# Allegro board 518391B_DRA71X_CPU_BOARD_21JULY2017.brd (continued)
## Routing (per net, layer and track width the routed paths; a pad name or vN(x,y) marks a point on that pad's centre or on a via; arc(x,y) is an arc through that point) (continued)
N30649045: length 1.8
  TOP w0.127: U44.8 158.47,31.43 v2(158.66,31.62)
  BOTTOM w0.127: 158.12,30.86 158.12,31.07 v2(158.66,31.62)
N30649515: length 4.2
  TOP w0.127: U44.6 156.68,30.06 v2(156.64,30.03) 157.08,29.59 157.35,29.59 C227.1
  BOTTOM w0.127: R379.1 156.97,30.36 v2(156.64,30.03)
N30674781: length 9.8
  TOP w0.127: R105.2 J10.1 ; U33.5 v2(153.15,56.64)
  BOTTOM w0.127: v2(153.15,56.64) 152.95,56.85 152.95,57.62 152.4,58.17 152.4,58.8 151.76,59.44 149.99,59.44 149.61,59.05 J10.1
N30703324: length 4.5
  TOP w0.254: R1.2 128.02,152.53 127.94,152.45 C7.1 125.71,151.04 U11.12
N30703458: length 2
  TOP w0.127: U11.19 122.31,148.47 122.05,148.21 R4.1
N30703463: length 2.3
  TOP w0.127: U11.20 122.57,147.97 121.67,147.07 R5.1
N30746595: length 1.8
  TOP w0.127: RJ1.2 128.27,149.61 128.13,149.46 U11.10
N30797231: length 1.6
  TOP w0.254: U20.6 105.33,116.72 105.45,116.84 C62.1
N30798114: length 1.7
  TOP w0.254: C245.1 92.46,25.38 92.51,25.43 92.33,25.61 U48.6
N30809211: length 5.1
  TOP w0.203: C220.2 R140.1 R141.2 88.04,32.61 88.04,34.04 88.3,34.29 U42.3
N30811250: length 6.8
  TOP w0.305: R182.2 161.8,15.19 161.49,15.49 U50.5 160.4,13.97 R177.1 RJ15.2
N30811520: length 2.2
  TOP w0.305: U50.3 C256.1
N30812987: length 2.4
  TOP w0.305: C255.1 153.16,18.03 U50.2
N30812990: length 1.5
  TOP w0.305: R163.1 151.13,19.68 C255.2
N30812993: length 1.8
  TOP w0.305: R163.2 154.18,19.94
N30813342: length 6
  TOP w0.305: R176.1 C257.1 R175.1 152.4,15.06 152.83,15.49 U50.4
N30813649: length 2.4
  TOP w0.305: R172.1 R175.2 C257.2
N30818369: length 4.1
  TOP w0.305: U43.14 146.98,30.18 147.57,29.59 R148.2 R149.2
N30818430: length 2.6
  TOP w0.305: R147.2 146.3,30.1 146.33,30.13 U43.13
N30818444: length 2.9
  TOP w0.305: R146.2 145.03,29.59 145.68,30.24 U43.12
N30819162: length 4.1
  TOP w0.305: R158.2 R159.2 139.95,21.46 140.54,20.87 U51.14
N30819197: length 1.4
  TOP w0.127: R159.1 TP58.1
N30819223: length 2.6
  TOP w0.305: R160.2 141.22,20.95 141.19,20.92 U51.13
N30819237: length 2.9
  TOP w0.305: U51.12 141.84,20.81 142.49,21.46 R161.2
N30821669: length 2.8
  TOP w0.203: U42.5 91.17,33.79 91.57,33.4 91.57,32.77 92.33,32
N31193882: length 2.3
  TOP w0.305: R14.1 44.74,136.23 Q6.4
N31194203: length 5.8
  TOP w0.305: Q4.4 v2(54.19,133.9) ; R20.1 v2(56.9,131.7)
  BOTTOM w0.305: v2(56.9,131.7) 55.5,131.7 54.19,133.01 v2(54.19,133.9)
N31194290: length 3.2
  TOP w0.305: Q5.4 57.87,132.88 58.17,132.59 R21.2
N31194295: length 6.3
  TOP w0.305: v2(64.26,136.23) 64.3,136.27 R15.2 ; Q7.4 v2(59.6,136.23)
  BOTTOM w0.305: v2(59.6,136.23) v2(64.26,136.23)
N31194655: length 2.3
  TOP w0.203: D9.1 45.03,112.83 R42.1
N31194670: length 7.3
  TOP w0.203: U19.2 49.38,111.79 ; 49.38,111.79 49.91,111.27 C67.1 ; 49.38,111.79 47.97,111.79 47.5,112.27 R42.2
N31194787: length 7.3
  TOP w0.305: D8.1 47.17,123.88 46.74,123.44 C50.1 48.89,122.55 50.03,121.42 U19.26
N31194818: length 7.3
  TOP w0.305: U19.20 53.93,121.5 54.23,121.79 C47.2 54.23,123.57 53.92,123.88 D6.1 53.92,126.75 D4.1
N31196095: length 3.7
  TOP w0.203: R37.1 60.07,120.14 59.93,120 59.33,120 C55.2 59.29,120.03 58.31,120.03 58.17,119.89 U19.15
N31196104: length 5.5
  TOP w0.203: R38.1 60.69,118.86 59.96,118.86 59.82,119 C55.1 58.29,119 57.91,118.62 56.77,118.62 56.54,118.85 U19.16
N31196146: length 8.7
  TOP w0.203: U19.7 52.63,112.58 v2(52.45,112.39) ; C74.1 v2(53.09,106.43)
  BOTTOM w0.203: v2(53.09,106.43) 52.45,107.06 v2(52.45,112.39)
N31196169: length 10.1
  TOP w0.203: R54.1 51.18,106.3 50.67,105.79 50.67,105.79 v2(50.67,105.78) ; U19.5 51.33,112.55 v2(51.12,112.33)
  BOTTOM w0.203: v2(50.67,105.78) 50.67,105.79 50.67,107.31 51.94,108.58 51.94,111.51 v2(51.12,112.33)
N31196187: length 10.3
  TOP w0.203: C76.2 v2(50.16,106.3) ; U19.6 51.98,112.94 51.82,112.78 51.82,112.01 51.31,111.51 v2(51.31,110.74) 51.31,110.24 51.43,110.11 R50.1
  BOTTOM w0.203: v2(50.16,106.3) 50.16,107.7 51.31,108.84 v2(51.31,110.74)
N31196205: length 10.4
  TOP w0.203: U19.4 50.68,112.66 50.55,112.52 v2(50.55,111.76) ; R53.1 v2(47.62,107.31) 47.24,107.7 R48.1
  BOTTOM w0.203: v2(50.55,111.76) 50.55,110.24 v2(47.62,107.31)
N31196259: length 4.4
  TOP w0.203: U19.9 53.93,111.17 R44.2 53.99,111.11 53.99,110.25 53.85,110.11 C69.1
N31196266: length 1.5
  TOP w0.203: R44.1 52.45,110.4 52.59,110.26 52.59,109.74 C68.1
N31197066: length 9.1
  TOP w0.203: U19.8 v2(53.28,112.39) ; C75.1 v2(54.8,106.43)
  BOTTOM w0.203: v2(54.8,106.43) 53.28,107.94 v2(53.28,112.39)
N31197134: length 6.8
  TOP w0.203: C70.2 48.64,109.98 v2(48.64,111) R45.2 ; U19.3 v2(50.03,112.39)
  BOTTOM w0.203: v2(50.03,112.39) v2(48.64,111)
N31197473: length 3.5
  TOP w0.203: TP14.1 R46.1 61.71,111.52 60.85,111.52 60.71,111.38 R43.2
N31206842: length 11.8
  TOP w0.305: U16.6 20.41,132.14 19.94,132.61 19.94,133.1 18.03,135 16.26,135 ; 16.26,135 15.75,134.49 15.75,133.09 16.05,132.79 U16.2 ; 16.26,135 Q3.4
N31206856: length 5.5
  TOP w0.305: U16.1 18.4,133.44 18.67,133.17 C30.1
N31206860: length 6
  TOP w0.305: U16.7 22.9,132.79 23.37,132.32 23.37,130.3 22.35,129.29 C30.2
N31206880: length 21.3
  TOP w0.635: L4.1 26.66,136.52 ; L4.1 23.38,136.52 ; L4.1 25.02,138.16 ; L4.1 25.02,134.89
  BOTTOM w0.127: v2(21.08,141.1) 19.05,143.13 11.68,143.13 11.18,143.64 11.18,146.05 10.67,146.56 10.03,146.56
N31207095: length 2.1
  TOP w0.127: v2(8.25,146.56) 8.41,146.71 DS1.2
  BOTTOM w0.127: v2(8.25,146.56) R202.1
N31208453: length 2.7
  TOP w0.203: U18.13 v2(81.28,126.87)
  BOTTOM w0.203: v2(81.28,126.87) 81.28,128.02 R213.2
N31208462: length 2
  TOP w0.203: v2(80.52,127.76) 80.12,127.37 U18.14
  BOTTOM w0.203: v2(80.52,127.76) 80.77,128.02 R214.1
N31208471: length 2.9
  TOP w0.203: v2(82.42,123.57) 81.77,124.22 U18.8
  BOTTOM w0.203: R219.2 82.93,123.06 v2(82.42,123.57)
N31208480: length 1.8
  TOP w0.203: v2(81.79,123.06) 81.79,123.52 81.58,123.72 U18.7
  BOTTOM w0.203: R220.1 v2(81.79,123.06)
N31208503: length 13.8
  LY3 w0.305: v2(93.81,122.47) 92.63,121.28 v2(83.69,121.28)
  BOTTOM w0.305: v2(83.69,121.28) R219.1 R220.2 ; Q10.4 v2(93.81,122.47)
N31208524: length 7.6
  BOTTOM w0.305: R214.2 R213.1 82.5,129.67 82.8,129.36 82.8,128.52 85.18,126.15 Q9.4
N31208551: length 15.6
  TOP w0.203: U18.12 81.89,126.21 82.17,126.49 v2(82.17,127) 82.8,127.63 C39.1 ; R18.1 v2(78.61,132.46)
  LY4 w0.203: v2(82.17,127) 80.77,128.4 80.77,130.3 v2(78.61,132.46)
  BOTTOM w0.203: v2(82.17,127) 85.72,123.44
  vias: v2(87.12,124.21) v2(87.12,123.32) v2(87.88,124.21) v2(87.88,123.32) v2(88.65,124.21) v2(88.65,123.32) v2(90.3,124.21) v2(90.3,123.44) v2(90.3,122.68) v2(91.19,124.21) v2(91.19,123.44) v2(91.19,122.68)
N31208672: length 3.8
  TOP w0.203: D5.1 C39.2 82.79,125.71 U18.11
N31208960: length 1.4
  BOTTOM w0.508: 88.65,119.89 R225.1
N31209649: length 6.2
  TOP w0.203: R18.2 R428.1 C36.2 76.71,128.52 78.13,127.1 U18.18
N31209654: length 4.8
  TOP w0.203: U18.17 78.63,127.37 77.72,128.27 C36.1 R22.1 R428.2
N31222073: length 5.2
  TOP w0.203: U18.23 77.01,124.22 76.71,123.92 v2(76.71,123.32) 75.95,122.55 C48.2
  BOTTOM w0.203: R401.1 76.07,122.68 v2(76.71,123.32)
  BOTTOM w0.254: R218.1 v2(76.71,123.32)
N31222132: length 1.4
  TOP w0.203: R29.1 75.44,124.97 C41.2
N31222198: length 3.5
  TOP w0.203: U18.20 76.85,125.71 76.45,126.11 R29.2 74.3,126.11 C40.1
N31222241: length 3.5
  TOP w0.203: C51.2 75.95,121.41 77.47,122.94 U18.24
N31222246: length 2.5
  TOP w0.203: U18.22 76.97,124.72 75.95,123.7 C43.2
N31222265: length 3.6
  TOP w0.203: R36.2 R35.1 81.47,121.48 81.47,121.86 80.62,122.71 U18.6
N31222285: length 3.4
  TOP w0.203: U18.5 80.12,122.57 80.47,122.23 80.47,121.61 C54.2 R34.1
N31222303: length 2.1
  TOP w0.203: v2(79.76,122.05) 79.62,122.18 U18.4
  BOTTOM w0.203: R222.2 v2(79.76,122.05)
N31222717: length 1.1
  TOP w0.203: R24.2 R23.1
N31223527: length 2.4
  BOTTOM w0.305: v2(86.49,137.54) 86.87,137.92 R211.1 R209.1
N31223584: length 3.9
  TOP w0.305: U15.5 92.02,138.23 92.08,138.18 v2(92.08,137.92) C27.1
  BOTTOM w0.305: R210.1 v2(92.08,137.92)
N31223889: length 1.3
  TOP w0.305: R16.1 C26.2
N31224124: length 3.4
  TOP w0.127: v2(95.25,145.67) 94.81,145.23 U15.9
  BOTTOM w0.127: R204.2 R207.1 v2(95.25,145.67)
N31225374: length 4.3
  TOP w0.127: R10.2 126.62,144.02 126.62,146.15 126.21,146.56 U11.6
N31225630: length 3.6
  TOP w0.305: U15.11 v2(92.67,146.52)
  BOTTOM w0.305: R208.2 92.67,145.33 v2(92.67,146.52)
N31225660: length 4.5
  TOP w0.305: RJ2.2 R17.1 93.6,137.41 93.22,137.41 92.67,137.96 U15.6
N31226612: length 6.8
  TOP w0.127: U15.7 93.32,138.2 v2(93.54,137.99)
  TOP w0.305: C28.2 91.82,137.22 v2(91.37,137.67) U15.4
  BOTTOM w0.127: v2(93.54,137.99) 92.84,137.29 91.75,137.29 v2(91.37,137.67)
N31272257: length 2.5
  TOP w0.127: 118.49,95.99 117.87,95.99 R59.2 ; 118.49,95.99 U24.2 ; 118.49,95.99 118.49,95.76 118.76,95.49 U24.3
N31313642: length 3.4
  TOP w0.127: U11.8 127.38,148.47 127.63,148.21 127.63,147.83 128.27,147.19 R8.2
N31313645: length 4.6
  TOP w0.127: U11.9 127.77,148.97 128.02,148.72 128.02,148.21 129.29,146.94 R9.2
N31432046: length 1.3
  TOP w0.127: R148.1 TP54.1
N31435823: length 2.3
  TOP w0.127: U37.44 v2(132.24,50.45)
  BOTTOM w0.127: R317.1 132.24,51.28 v2(132.24,50.45)
N31460069: length 3.1
  TOP w0.127: Q8.6 88.25,41.16 v2(88.52,40.89) 88.14,40.51 Q8.5
  BOTTOM w0.127: R370.1 88.39,41.02 v2(88.52,40.89)
N31485198: length 2.1
  TOP w0.127: R67.1 153.18,86.09 U25.21
N31485201: length 2.1
  TOP w0.127: U25.20 153.23,87.19 R65.1
N31485220: length 8.4
  TOP w0.127: U25.3 v2(168.38,84.99) ; v2(167.89,78.99) R69.2
  BOTTOM w0.127: v2(168.38,84.99) 168.38,79.48 v2(167.89,78.99)
N31486138: length 2.7
  TOP w0.127: U75.2 116.08,94.23 RJ5.2
N31555915: length 2.3
  BOTTOM w0.305: R211.2 R209.2 C265.1
N31573832: length 8.7
  TOP w0.508: C208.1 v2(69.6,36.07) ; RJ12.2 v2(65.02,36.83) L36.1 65.02,35.84
  BOTTOM w0.508: C516.1 v2(69.6,36.07) 68.83,36.83 v2(65.02,36.83)
N31594961: length 7.1
  TOP w0.305: R142.2 C206.2 ; C206.2 66.67,34.16 R137.2 ; C206.2 70.61,34.16 71.05,34.6 U41.3
N31595589: length 3.5
  TOP w0.127: U41.6 75.51,34.6 75.69,34.42 75.69,32.51 C218.1
N31598114: length 8.7
  TOP w0.508: L52.1 v2(65.02,29.34) RJ13.2 ; v2(69.6,28.59) C241.1
  BOTTOM w0.508: 69.6,27.69 v2(69.6,28.59) 68.85,29.34 v2(65.02,29.34)
N31598152: length 3.5
  TOP w0.127: U49.6 75.51,27.11 75.69,26.92 75.69,25.02 C246.1
N31598156: length 7.1
  TOP w0.305: R150.2 66.67,26.67 C236.2 ; C236.2 70.61,26.67 71.05,27.11 U49.3 ; C236.2 R157.2
N31635389: length 6.7
  TOP w0.127: P8.2 v2(10.08,12.52)
  BOTTOM w0.127: v2(10.08,12.52) 10.08,13.54 C534.2 11.29,13.59 U65.1 12.56,13.6 R399.1 12.7,13.46 C535.2
N31635587: length 8
  TOP w0.127: P8.3 v2(6.22,19.68)
  BOTTOM w0.127: v2(6.22,19.68) C532.1 7.48,18.41 U64.1 8.75,18.4 R396.2 R395.2 11.05,18.41 C531.2
N31636337: length 6.7
  TOP w0.127: P7.2 v2(10.08,23.95)
  BOTTOM w0.127: v2(10.08,23.95) 10.08,24.97 C529.2 11.29,25.02 U63.1 12.56,25.03 R392.1 12.7,24.89 C530.2
N31636510: length 8
  TOP w0.127: P7.3 v2(6.22,31.11)
  BOTTOM w0.127: C520.2 11.05,29.84 R385.2 R386.2 8.75,29.83 U62.1 7.48,29.84 C523.1 v2(6.22,31.11)
N31636885: length 6.7
  TOP w0.127: P6.2 v2(10.08,35.38)
  BOTTOM w0.127: v2(10.08,35.38) 10.08,36.4 C512.2 11.29,36.45 U61.1 12.56,36.46 R366.1 12.7,36.32 C513.2
N31637058: length 8
  TOP w0.127: P6.3 v2(6.22,42.54)
  BOTTOM w0.127: v2(6.22,42.54) C504.1 7.48,41.27 U60.1 8.75,41.26 R353.2 R352.2 11.05,41.27 C502.2
N31637886: length 6.7
  TOP w0.127: P4.2 v2(10.08,46.81)
  BOTTOM w0.127: C490.2 12.7,47.75 R326.1 12.56,47.89 U59.1 11.29,47.88 C489.2 10.08,47.83 v2(10.08,46.81)
N31638056: length 8
  TOP w0.127: P4.3 v2(6.22,53.97)
  BOTTOM w0.127: C473.2 11.05,52.7 R314.2 R315.2 8.75,52.69 U58.1 7.48,52.7 C476.1 v2(6.22,53.97)
N31638108: length 6.7
  TOP w0.127: P3.2 v2(10.08,58.24)
  BOTTOM w0.127: C449.2 12.7,59.18 R304.1 12.56,59.32 U57.1 11.29,59.31 C448.2 10.08,59.26 v2(10.08,58.24)
N31638278: length 8
  TOP w0.127: P3.3 v2(6.22,65.41)
  BOTTOM w0.127: v2(6.22,65.41) C439.1 7.48,64.13 U53.1 8.75,64.12 R294.2 R293.2 11.05,64.13 C438.2
N31691908: length 4
  TOP w0.127: R57.1 TP20.1 124.46,92.96 123.93,93.49 U24.10
N31691918: length 7.1
  TOP w0.127: U24.12 124.47,94.49 124.71,94.74 TP22.1 126.87,94.74 R58.1 R60.1
N31691928: length 6.9
  TOP w0.127: U24.13 124.08,94.99 124.71,95.63 TP23.1 126.87,95.88 R62.1 R61.1
N31691937: length 6.1
  TOP w0.127: U75.4 v2(114.71,90.45)
  LY3 w0.133: TP24.1 118.24,90.3 117.94,90 115.15,90 v2(114.71,90.45)
  BOTTOM w0.127: R63.1 115.42,90.45 v2(114.71,90.45)
N31767762: length 2.5
  TOP w0.127: v2(133.22,53.21) 132.74,52.73 U37.43
  BOTTOM w0.127: v2(133.22,53.21) R316.2
N31975868: length 16.5
  TOP w0.127: U27.F20 v1(88.09,79.83)
  LY4 w0.133: v1(88.09,79.83) 88.7,79.23 88.7,77.9 85.7,74.9 84.71,74.9 84.14,74.34 83.51,74.34 82.59,73.43 82.37,73.43 81.88,72.94 77.51,72.94 TP32.1
N32186036: length 1.6
  TOP w0.254: U39.6 69.21,43.98 69.09,44.11 C174.1
N32241906: length 2
  TOP w0.127: R168.1 67.22,13.25 v2(67.22,13.93)
  BOTTOM w0.127: v2(67.22,13.93) 67.49,13.67 J19.119
N32242118: length 5.6
  TOP w0.127: RJ30.3 v2(80.26,22.61)
  BOTTOM w0.127: v2(80.26,22.61) 80.26,21.08 79.49,20.31 J19.22
N32242181: length 3.3
  BOTTOM w0.127: TP61.1 85.6,19.68 85.49,19.57 J19.32
N32242306: length 1.9
  TOP w0.127: v2(92.74,13.94) 92.74,13.23 R165.1
  BOTTOM w0.127: v2(92.74,13.94) 92.68,13.89 J19.77
N32242319: length 1.5
  TOP w0.127: D20.1 R169.1
N32242321: length 2.6
  TOP w0.127: v2(92.96,19.81) D20.2
  BOTTOM w0.127: J19.45 93.28,19.49 v2(92.96,19.81)
N32242323: length 3.7
  BOTTOM w0.127: J19.76 93.28,14.41 92.33,15.37 TP59.1
N32242357: length 1.9
  TOP w0.127: R164.1 95.09,13.24 v2(95.09,13.94)
  BOTTOM w0.127: v2(95.09,13.94) 95.08,13.93 J19.73
N32242411: length 2.2
  TOP w0.127: v2(100.2,19.43) 100.33,19.3 R184.1
  BOTTOM w0.127: J19.57 100.48,19.16 v2(100.2,19.43)
N32256405: length 2.6
  TOP w0.127: RJ14.2 94.87,17.65 94.53,17.31 v2(94.53,16.93)
  BOTTOM w0.127: v2(94.53,16.93) 94.48,16.98 J19.47
N32396399: length 5.6
  TOP w0.127: U33.47 156.56,54.32 158.37,56.13 159.51,56.13 TP38.1
N32396462: length 5.2
  BOTTOM w0.127: TP43.1 158.37,43.18 158.37,45.59 R336.2 157.99,46.99
N32396466: length 4.9
  BOTTOM w0.127: TP44.1 158.75,42.42 158.75,45.72 R336.1 159,46.99
N32396489: length 4.2
  TOP w0.127: v2(157.1,50.16) 156.94,50.32 U33.39
  BOTTOM w0.127: C491.1 158.62,48.39 158.62,48.64 v2(157.1,50.16)
N32396498: length 3.5
  TOP w0.127: U33.38 156.68,49.82 v2(156.97,49.53)
  BOTTOM w0.127: v2(156.97,49.53) 157.23,49.53 158.24,48.51 158.24,48.26 C492.1
N32412234: length 6.8
  TOP w0.127: R110.2 157.99,54.86 157.61,54.48 ; 157.61,54.48 157.61,52.45 157.35,52.2 156.84,52.2 156.72,52.32 U33.43 ; 157.61,54.48 157.4,54.48 156.73,53.82 U33.46
N32413360: length 2.4
  TOP w0.127: v2(80.77,19.56) 80.77,18.54
  BOTTOM w0.127: J19.24 80.69,19.47 v2(80.77,19.56)
N32413363: length 2.4
  TOP w0.127: v2(81.53,19.43) 81.91,19.05 81.91,18.54
  BOTTOM w0.127: v2(81.53,19.43) 81.29,19.18 J19.25
N32592449: length 13.5
  TOP w0.127: U27.E19 v1(89.43,79.22)
  LY4 w0.133: v1(89.43,79.22) 88.93,78.73 88.93,77.75 85.82,74.64 84.82,74.64 84.25,74.08 83.61,74.08 82.7,73.16 82.47,73.16 81.83,72.52 v2(80.52,72.52)
  BOTTOM w0.127: R267.2 v2(80.52,72.52)
N32593135: length 12.9
  TOP w0.102: U27.B5 98.49,77.23 98.49,76.17
  TOP w0.127: R99.2 106.05,68.38 98.49,75.94 98.49,76.17
N32593759: length 21.5
  TOP w0.127: v2(118.11,76.54) 118.41,76.83 R73.2 ; U27.G3 v1(99.79,80.48)
  LY3 w0.133: v2(118.11,76.54) 105.83,76.54 103.51,78.86 101.41,78.86 v1(99.79,80.48)
N32595277: length 17.1
  TOP w0.102: 84.4,82.29 84.6,82.29 84.74,82.43 85.49,82.43 85.49,82.43 U27.K24
  TOP w0.127: 84.4,82.29 82.8,82.29 81.28,80.77 78.99,80.77 77.09,78.87 77.09,78.58 76.87,78.36 v2(76.83,78.36)
  BOTTOM w0.127: R402.1 C375.2 ; C375.2 v2(76.83,78.36) ; C375.2 R263.1 R262.1
N32733566: length 3
  TOP w0.127: U30.24 v2(144.12,69.82)
  BOTTOM w0.127: R274.2 R275.1 144.12,70.84 v2(144.12,69.82)
N32807371: length 2.7
  TOP w0.305: U30.14 144.79,64.04 145.2,63.63 146.3,63.63 C129.1
N32807372: length 4.2
  TOP w0.305: U30.7 140.84,62.04 140.84,62.03 140.84,61.61 140.84,61.61 140.84,61.57 140.83,61.56 140.83,61.14 140.84,61.14 140.84,60.46 C131.1 C132.1
N32807373: length 2.7
  TOP w0.305: C127.1 146.3,65.15 145.16,65.15 144.77,65.54 U30.17
N32830609: length 4.6
  TOP w0.127: TP67.1 123.82,93.85 v2(123.7,93.98) 123.69,93.99 U24.11
  BOTTOM w0.127: R427.1 v2(123.7,93.98)
N32837329: length 1.8
  TOP w0.305: v2(145.03,68.83) 144.74,68.54 U30.23
  BOTTOM w0.305: C410.1 v2(145.03,68.83)
N32856854: length 2.5
  TOP w0.112: C124.1 146.1,66.98 144.8,66.98 144.74,67.04 U30.20
N32867532: length 2.5
  TOP w0.112: C125.1 146.1,66.62 144.82,66.62 144.74,66.54 U30.19
N32916975: length 3
  TOP w0.127: v2(140.33,61.82) 140.34,61.82 140.34,61.98 140.34,61.98 U30.6
  BOTTOM w0.127: v2(140.33,61.82) 140.34,61.82 R298.1 R297.2
N33050083: length 13.3
  TOP w0.127: U27.AC3 v1(99.79,90.88)
  LY3 w0.133: v2(109.09,94.49) 108.46,95.12 102.82,95.12 99.79,92.09 v1(99.79,90.88)
  BOTTOM w0.127: R429.2 v2(109.09,94.49)
N33095449: length 8.4
  BOTTOM w0.127: R433.1 79.15,112.88 U76.3 78.25,114.41 77.34,115.32 75.82,115.32 74.97,116.17 Q12.3
N33095497: length 14
  BOTTOM w0.127: D24.1 76.76,109.65 76.96,109.85 76.96,110.88 U76.5 76.43,110.9 75.82,111.51 75.82,114.55 74.93,115.44 73.28,115.44 73.03,115.7 Q12.2 R432.1 C553.1 R431.1
N33095499: length 4.5
  BOTTOM w0.127: Q12.5 73.03,113.69 72.9,113.56 72.5,113.56 72.37,113.69 Q12.6 71.21,114.21 70.87,114.55 R430.1
N33164061: length 5.1
  TOP w0.305: U30.21 144.13,67.54 145.26,67.54 v2(146.69,68.96) C123.1
  BOTTOM w0.305: R290.2 v2(146.69,68.96)
N312234419: length 2.9
  TOP w0.305: 90.3,136.52 C26.1 90.3,137.16 90.72,137.58 U15.3
N3026308320: length 14.2
  TOP w0.102: 94.59,76.17 94.59,77.24 U27.B11
  TOP w0.127: 94.59,76.17 94.59,74.27 94.23,73.91 94.23,73.28 95.5,72.01 96.77,72.01 97.26,71.53 97.26,70.89 97.54,70.61 98.04,70.61 100.84,67.82 R101.2

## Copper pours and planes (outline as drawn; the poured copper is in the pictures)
GND on TOP (solid shape): 4.32,56.77 0.89,56.77 0.89,59.82 4.32,59.82
GND on TOP (solid shape): 4.32,45.34 0.89,45.34 0.89,48.39 4.32,48.39
GND on TOP (solid shape): 4.32,33.91 0.89,33.91 0.89,36.96 4.32,36.96
GND on TOP (solid shape): 4.32,22.48 0.89,22.48 0.89,25.53 4.32,25.53
GND on TOP (solid shape): 4.32,11.05 0.89,11.05 0.89,14.1 4.32,14.1
GND on TOP: 33.4,57.4 33.4,44.32 33.15,44.07 23.24,44.07 22.86,44.45 22.86,54.48 22.61,54.74 22.61,56.01 22.23,56.39 19.05,56.39 19.05,28.07 21.97,25.15 21.97,19.68 18.8,16.51 18.8,10.92 19.05,10.67 54.36,10.67 54.36,17.78 56.52,19.94 60.33,19.94 60.33,48.64 57.15,51.82 57.15,57.4 ; 6 cut-outs
GND on TOP: 58.04,109.09 57.66,109.47 56.9,109.47 56.52,109.09 48.39,109.09 48.13,108.84 48.13,108.33 48.77,107.7 49.02,107.7 49.02,107.19 49.28,106.93 55.12,106.93 56.13,105.92 60.96,105.92 60.96,108.33 60.2,109.09
GND on TOP: 134.37,102.62 137.03,99.95 160.78,99.95 164.97,95.76 164.97,94.87 165.86,93.98 172.21,93.98 172.21,108.84 174.88,108.84 174.88,110.36 172.08,110.36 172.08,123.32 144.02,123.32 142.37,124.97 134.37,124.97
GND on TOP: 146.94,25.02 146.94,20.07 145.29,18.41 140.34,18.41 139.83,18.92 139.83,20.7 138.94,21.59 138.05,21.59 137.79,21.34 137.79,14.22 138.3,13.72 139.7,13.72 140.08,14.1 140.08,14.73 140.34,14.99 145.16,14.99 146.18,13.97 146.18,12.7 146.69,12.19 148.84,12.19 149.22,12.57 149.22,25.02
GND on TOP: 83.82,35.56 87.88,35.56 88.27,35.18 89.28,35.18 89.28,33.15 88.77,32.64 88.77,32.26 89.15,31.88 90.3,31.88 90.55,32.13 90.55,33.02 90.04,33.53 90.04,37.72 89.66,38.1 84.33,38.1 83.44,37.21 83.44,35.94
GND on TOP: outline of 83 points within 0.76,61.47 169.42,168.66
GND on TOP: 29.84,103.63 29.84,106.04 30.73,106.04 30.73,103.63
GND on TOP: 2.29,73.15 20.7,73.15 26.03,67.82 31.37,67.82 32.64,69.09 32.64,69.21 34.04,70.61 34.04,76.33 31.88,76.33 31.88,85.98 33.4,85.98 33.4,86.61 31.88,86.61 31.88,92.96 33.02,92.96 33.02,99.57 29.84,102.74 26.29,102.74 20.07,96.52 2.41,96.52 0.89,95 0.89,74.55
GND on TOP: 156.08,14.48 156.08,18.92 156.72,19.56 156.72,22.35 157.35,22.99 160.78,22.99 161.8,24 161.93,24 162.69,24.76 162.69,25.78 163.07,26.16 164.85,26.16 165.86,25.15 165.86,24 169.42,24 169.42,10.79 55.24,10.79 55.24,17.14 57.28,19.18 61.59,19.18 63.25,17.53 63.25,12.83 104.01,12.83 105.54,14.35 105.54,16.76 107.82,19.05 130.56,19.05 136.78,12.83 154.94,12.83 154.81,12.95 154.81,13.97 155.32,14.48
GND on TOP: 140.59,26.03 140.59,30.99 142.24,32.64 147.19,32.64 147.7,32.13 147.7,30.35 148.59,29.46 149.48,29.46 149.73,29.72 149.73,31.88 150.62,32.77 158.24,32.77 158.24,36.07 153.16,36.07 151.89,37.34 150.62,37.34 149.86,38.1 149.86,40 150.5,40.64 152.15,40.64 152.4,40.89 152.4,42.29 152.15,42.54 145.67,42.54 145.03,41.91 145.03,40.13 145.54,39.62 146.43,39.62 147.45,38.61 147.45,36.32 147.19,36.07 142.37,36.07 141.35,37.08 141.35,38.35 140.84,38.86 139.45,38.86 138.3,37.72 138.3,26.03
GND on TOP: 41.91,71.25 39.62,68.96 39.62,63.88 38.73,62.99 28.07,62.99 23.88,58.8 21.21,58.8 19.69,60.32 18.03,60.32 17.02,59.31 17.02,28.32 21.08,24.26 21.08,20.07 18.03,17.02 18.03,10.67 0.64,10.67 0.64,68.83 2.29,70.48 19.81,70.48 23.11,67.18 31.5,67.18 35.05,70.74 35.05,74.8 35.12,74.87 35.12,76.14 36.58,77.6 41.66,77.6 41.91,77.34
GND on TOP: 42.29,128.27 42.29,113.03 69.34,113.03 70.87,114.55 70.87,128.27 56.64,128.27 56.2,128.71 56.2,129.1 56.26,129.16 56.26,129.67 55.37,130.56 51.18,130.56 51.18,128.91 50.55,128.27 ; 1 cut-out
GND on TOP: 94.61,27.94 94.87,27.69 94.87,27.18 91.95,27.18 91.95,26.03 91.69,25.78 91.69,24.64 91.44,24.38 90.93,24.38 90.68,24.64 90.68,27.94
GND on TOP: 70.48,33.4 70.48,31.88 69.72,31.11 67.69,31.11 67.31,31.5 67.31,32.13 67.44,32.26 68.2,32.26 68.58,32.64 68.58,33.4 68.83,33.65 70.23,33.65
GND on TOP: 70.48,25.91 70.48,24.38 69.72,23.62 67.69,23.62 67.31,24 67.31,24.64 67.44,24.76 68.2,24.76 68.58,25.15 68.58,25.91 68.83,26.16 70.23,26.16
GND on TOP: 66.93,41.66 66.67,41.91 66.67,42.42 69.6,42.42 69.6,43.56 69.85,43.81 69.85,44.96 70.1,45.21 70.61,45.21 70.87,44.96 70.87,41.66
GND on TOP: 167.89,54.48 156.72,54.48 156.72,42.93 156.97,42.67 168.02,42.67 168.53,42.16 168.53,29.08 168.02,28.57 168.02,28.19 168.53,27.69 168.53,23.75 169.42,23.75 169.42,27.56 169.16,27.81 169.42,27.81 169.42,61.59 168.02,61.59 167.89,61.47
GND on BOTTOM: 75.86,48.41 75.86,64.81 91.57,64.81 94.3,62.08 94.3,48.41
GND on BOTTOM: 122.81,95.63 122.81,68.58 118.49,64.26 51.94,64.26 50.16,66.04 50.16,91.57 51.69,93.09 51.69,104.01 51.56,104.14 52.45,105.03 107.31,105.03 109.6,102.74 115.7,102.74 ; 12 cut-outs
GND on BOTTOM: 47.31,168.47 47.37,168.53 169.16,168.53 169.16,126.36 132.97,126.36 123.57,116.97 123.57,102.23 123.44,102.11 105.79,102.11 102.62,105.28 51.69,105.28 51.18,104.78 51.18,93.34 49.78,91.95 49.78,74.8 46.35,71.37 46.35,65.41 45.85,64.9 39.62,64.9 37.97,63.25 23.88,63.25 23.11,62.48 23.24,62.36 23.24,59.05 22.61,58.42 20.45,58.42 19.94,58.93 19.94,59.56 15.24,64.26 9.14,64.26 7.87,62.99 7.87,35.81 8.64,35.05 16.13,35.05 17.65,33.53 17.65,26.03 20.7,22.99 20.7,10.67 0.76,10.67 0.64,10.79 0.64,68.45 2.29,70.1 19.69,70.1 23.11,66.67 30.35,66.67 40.64,76.96 41.91,76.96 43.05,78.1 43.05,101.47 41.27,103.25 24.13,103.25 18.41,97.54 0.64,97.54 0.7,97.6 0.7,115.63 0.64,115.7 0.64,168.15 0.95,168.47 ; 3 cut-outs
GND on BOTTOM: 21.72,10.79 21.72,23.49 18.67,26.54 18.67,43.94 36.58,43.94 40.39,47.75 55.37,47.75 56.13,46.99 56.13,41.66 60.83,36.96 60.83,20.32 57.66,20.32 54.74,17.4 54.74,10.79
GND on BOTTOM: 2.79,71.5 20.57,71.5 24.64,67.44 29.46,67.44 36.2,74.17 36.2,91.82 34.16,93.85 34.16,97.66 30.23,101.6 24.26,101.6 19.43,96.77 2.29,96.77 0.89,95.38 0.89,73.41
GND on BOTTOM: 134.24,125.48 134.24,99.69 134.37,99.57 162.31,99.57 168.02,93.85 172.21,93.85 172.21,123.44 170.18,125.48
GND on BOTTOM: 55.5,10.79 55.5,17.14 57.53,19.18 60.96,19.18 63.12,17.02 63.12,13.21 104.39,13.21 106.17,14.99 106.17,17.53 108.08,19.43 112.52,19.43 120.65,11.3 147.7,11.3 147.7,17.4 155.45,25.15 168.27,25.15 168.78,25.65 168.78,34.42 159.77,43.43 159.77,53.97 153.67,60.07 153.67,89.79 149.86,93.6 129.79,93.6 129.79,83.95 126.87,81.03 121.92,81.03 115.44,87.5 115.44,102.49 118.49,105.54 124.21,105.54 124.71,106.04 124.71,116.33 129.67,121.28 133.6,121.28 133.6,98.81 158.88,98.81 159,98.68 159,77.34 162.94,77.34 162.94,92.71 169.42,92.71 169.42,10.79
GND on L2_GND: 169.42,10.79 0.69,10.79 0.69,168.66 169.42,168.66
GND on LY3: 89.15,82.04 89.15,81.79 89.41,81.53 90.42,81.53 90.93,81.03 91.44,81.03 91.95,81.53 95.12,81.53 95.76,80.9 96.52,80.9 96.65,81.03 96.65,81.15 95.5,82.3 95.5,82.55 96.14,83.19 96.14,83.82 95.88,84.07 95.25,84.07 94.49,83.31 94.49,83.06 94.23,82.8 93.47,82.8 92.96,83.31 90.68,83.31 89.92,82.55 89.92,82.3 89.66,82.04
GND on LY3: 140.46,153.16 140.46,164.34 136.53,168.27 97.16,168.27 95.88,167 95.88,151.64 98.81,148.72 104.52,148.72 106.43,146.81 134.11,146.81
VBAT on TOP: 13.08,142.75 13.08,135.38 12.06,134.37 5.84,134.37 4.83,135.38 4.83,143.76 6.1,145.03 10.8,145.03
VBAT on LY3, LY4: 5.21,132.97 13.08,132.97 15.49,135.38 15.49,166.62 14.48,167.64 2.92,167.64 0.89,165.61 0.89,137.29
VBAT_A on TOP: 22.48,85.22 26.42,85.22 26.42,83.95 26.16,83.69 25.15,83.69 24.64,84.2 22.48,84.2
VBAT_A on TOP: 42.93,135.89 36.58,135.89 34.67,137.8 34.67,144.02 35.94,145.29 45.09,145.29 46.61,143.76 46.61,138.68 45.72,137.8 43.56,137.8 42.93,137.16
VBAT_A on TOP: 22.35,76.96 26.29,76.96 26.29,75.56 26.03,75.31 24.89,75.31 24.38,75.82 22.35,75.82
VBAT_A on TOP: 33.91,77.6 29.97,77.6 29.97,76.33 30.23,76.07 31.24,76.07 31.75,76.58 33.91,76.58
VBAT_A on TOP: 22.48,92.46 26.42,92.46 26.42,93.85 26.16,94.11 25.02,94.11 24.51,93.6 22.48,93.6
VBAT_A on BOTTOM: 23.37,85.22 23.37,83.95 24,83.31 25.4,83.31 26.03,82.68 29.46,82.68 29.72,82.93 29.72,84.84 29.34,85.22 26.54,85.22 26.29,85.47 23.62,85.47
VBAT_A on BOTTOM: 23.75,92.2 26.16,92.2 26.67,92.71 29.59,92.71 29.84,92.96 29.84,94.87 29.59,95.12 24.64,95.12 23.37,93.85 23.37,92.58
VBAT_A on BOTTOM: 23.24,76.96 23.24,75.69 23.88,75.06 34.04,75.06 34.8,75.82 34.8,77.72 34.67,77.85 31.88,77.85 31.11,78.61 30.23,78.61 29.72,78.1 29.72,77.47 29.46,77.22 23.49,77.22
VBAT_A on LY3: 42.42,117.98 45.47,121.03 45.47,140.97 43.94,142.49 32.64,142.49 24.77,134.62 24.77,75.82 25.27,75.31 30.86,75.31 31.62,76.07 31.62,90.42 42.42,101.22
VBAT_F on TOP: 50.42,129.16 41.66,129.16 41.66,113.16 43.12,111.7 44.13,111.7 44.58,111.25 44.58,107.95 43.31,106.68 36.2,106.68 31.37,111.51 4.19,111.51 4.19,116.97 9.14,116.97 14.1,121.92 26.16,121.92 29.97,125.73 29.97,132.72 32.77,135.51 50.42,135.51
VBAT_PM on TOP: 17.53,135.64 16.51,134.62 16.51,132.84 17.53,131.83 17.53,129.29 14.99,129.29 13.72,130.56 13.72,143 11.81,144.91 11.81,149.1 12.45,149.73 17.53,149.73
VBAT_PM on BOTTOM: 16.13,143.89 16.13,149.61 11.94,149.61 11.94,143.89
VBAT_SYS on TOP: 96.39,127.89 96.39,130.94 87.12,130.94 86.11,129.92 86.11,127.13 86.49,126.75 88.52,126.75 89.66,127.89
VBAT_SYS on TOP: 16.51,155.32 40.77,155.32 47.12,148.97 63.88,148.97 63.88,137.67 65.66,135.89 70.1,135.89 73.03,132.97 78.11,132.97 79.12,131.95 79.12,128.02 79.38,127.76 79.38,126.49 79.76,126.49 79.76,127.51 81.15,128.91 81.15,130.3 81.53,130.68 83.95,130.68 84.84,129.79 86.87,129.79 87.5,130.43 87.5,131.32 83.57,135.25 77.22,135.25 76.58,135.89 76.58,158.12 73.53,161.16 18.03,161.16 16.51,159.64
VBAT_SYS on TOP: 109.73,22.73 107.82,22.73 107.82,19.68 109.73,19.68
VBAT_SYS on BOTTOM: 88.9,126.87 85.6,126.87 83.44,129.03 83.44,129.92 83.19,130.18 80.64,130.18 80.26,129.79 80.26,127.38 75.82,127.38 74.93,126.49 74.93,125.6 75.95,124.59 75.95,123.82 75.69,123.57 72.14,123.57 71.63,124.08 71.63,134.49 69.6,136.52 69.6,138.56 69.66,138.62 69.66,141.8 62.99,148.46 46.23,148.46 40.13,154.56 18.92,154.56 17.27,156.21 17.27,159.89 19.05,161.67 48.39,161.67 77.98,161.8 78.49,161.29 78.49,136.78 79.25,136.02 91.31,136.02 91.31,129.29
VBUS1_5V0 on TOP: 124.46,149.73 123.44,149.73 123.44,149.86 122.68,149.86 121.6,150.94 121.6,157.48 123.95,157.48 123.95,152.15 124.46,151.64
VBUS1_5V0 on BOTTOM: 148.34,154.81 149.35,153.8 149.61,153.8 150.24,154.43 150.24,159.38 147.95,161.67 123.57,161.67 121.54,159.64 121.54,151.13 123.44,149.22 135.51,149.22 141.1,154.81
VBUS2_5V0 on TOP: 155.83,149.61 156.59,149.61 156.84,149.86 156.84,151.64 158.12,152.91 158.12,154.31 159.64,155.83 159.64,160.66 158.37,161.93 156.46,161.93 155.83,161.29 155.83,152.65 155.57,152.4 155.57,149.86
VDD_1P8 on LY4: 159.89,58.55 159.89,49.53 156.46,46.1 153.8,46.1 153.16,46.74 153.16,52.32 156.72,55.88 156.72,58.42 157.23,58.93 159.51,58.93
VDD_1P8_FPD on LY3: 152.53,46.48 156.59,46.48 157.73,47.62 157.73,51.43 157.23,51.94 154.94,51.94 151.89,48.89 151.89,47.12
VDD_1V8_SW on TOP: 82.04,55.75 80.52,55.75 78.61,53.85 76.07,53.85 75.69,54.23 75.69,57.15 75.95,57.4 78.99,57.4 80.26,56.13 81.15,56.13 81.28,56.01 82.04,56.01
VDD_CORE_AVS on TOP: 86.32,45.77 93.08,45.77 93.15,45.69 93.15,42.9 92.82,42.57 86.68,42.57 86.32,42.92
VDD_CORE_AVS on LY3: 89.79,87.63 89.79,85.6 89.28,85.09 89.28,84.96 89.66,84.58 89.66,83.81 89.17,83.31 89.17,82.31 89.26,82.22 89.53,82.22 89.66,82.35 89.66,82.55 90.68,83.57 92.98,83.57 93.61,82.94 93.62,82.93 93.73,82.93 93.74,82.95 94.11,82.95 94.12,82.94 94.23,83.06 94.23,83.31 95,84.07 95,85.13 96.22,86.34 96.22,87.41 95.11,88.52 91.31,88.52 90.68,87.88 90.04,87.88
VDD_CORE_AVS on LY5_PWR: 95.63,82.42 91.69,82.42 91.06,81.79 88.65,81.79 87.76,82.68 87.76,83.69 89.41,85.34 89.41,87.25 90.68,88.52 92.71,88.52 93.22,89.03 93.22,92.96 100.33,92.96 101.6,94.23 111.51,94.23 112.53,93.21 112.53,76.08 112.53,76.07 112.53,42.54 86.54,42.54 86.23,42.85 86.23,48.89 87.63,50.29 88.65,50.29 90.04,51.69 91.06,51.69 92.58,53.21 92.58,66.55 92.84,66.8 94.11,66.8 94.36,66.55 95.25,66.55 95.5,66.8 97.03,66.8 97.28,67.06 99.69,67.06 99.95,67.31 102.36,67.31 103.5,68.45 103.5,69.47 104.01,69.98 104.01,72.01 104.52,72.52 104.52,73.79 104.65,73.91 104.65,74.55 104.52,74.68 104.52,77.09 101.73,79.88 101.73,81.53 100.2,83.06 96.27,83.06
VDD_CORE_SW on TOP: 85.34,52.65 85.34,47.88 85.98,47.24 89.15,47.24 89.41,47.5 89.41,49.78 88.9,50.29 87,50.29 85.59,51.7 85.59,52.65
VDD_DDR_1V35 on TOP: 63.5,50.8 63.25,50.8 63.25,52.83 62.86,53.21 62.86,60.71 63.37,61.21 65.41,61.21 66.04,60.58 66.04,60.2 65.15,59.31 65.15,55.88 64.64,55.37 64.64,52.07 64.26,51.69 63.5,51.69
VDD_DDR_1V35 on TOP: 77,45.74 83.76,45.74 83.83,45.66 83.83,42.87 83.5,42.54 77.36,42.54 77,42.9
VDD_DDR_1V35 on BOTTOM: 65.28,68.33 47.88,68.33 47.5,67.94 47.5,66.04 47.88,65.66 58.29,65.66 59.69,64.26 59.69,61.59 60.96,60.32 65.79,60.32 66.29,60.83 66.29,67.31
VDD_DDR_1V35 on LY5_PWR: 89.15,86.11 89.15,87.25 90.68,88.77 92.71,88.77 92.84,88.9 92.84,105.73 43.56,105.73 43.56,103.12 42.42,101.98 42.42,43.48 43.33,42.57 83.49,42.57 83.67,42.75 83.67,46.63 76.96,53.34 67.69,53.34 66.29,54.74 66.29,59.05 66.04,59.31 66.04,60.32 66.29,60.58 66.29,74.93 69.22,77.85 77.09,77.85 82.17,82.93 84.84,82.93 85.34,83.44 85.34,84.71 85.72,85.09 88.14,85.09
VDD_DDR_SW on TOP: 85.09,52.7 85.09,48.01 84.33,47.24 81.28,47.24 81.03,47.5 81.03,49.78 82.04,50.8 84.33,50.8 84.85,51.32 84.85,52.7
VDD_DSP_AVS on TOP: 83.38,66.52 76.62,66.52 76.54,66.59 76.54,69.39 76.87,69.72 83.02,69.72 83.38,69.36
VDD_DSP_AVS on BOTTOM: 92.46,82.04 93.22,82.8 94.61,82.8 95,82.42 95,81.28 93.98,80.26 92.46,80.26 91.69,81.03 91.69,81.28 91.82,81.41 92.08,81.41 92.46,81.79
VDD_DSP_AVS on BOTTOM: 98.17,70.74 98.17,72.14 98.55,72.52 103.12,72.52 103.63,73.02 103.63,73.66 101.35,75.95 99.06,75.95 97.41,74.3 97.41,70.74
VDD_DSP_AVS on LY3: 77.55,78.16 76.38,76.99 76.38,68.93 76.93,68.38 84.33,68.38 84.79,68.83 84.79,72.59 86.23,74.04 86.23,76.71 84.79,78.16
VDD_DSP_AVS on LY4: 92.33,82.17 92.33,81.41 92.58,81.15 92.96,81.15 93.34,80.77 93.34,74.93 92.33,73.91 91.95,73.91 91.69,73.66 91.69,70.61 91.19,70.1 77.09,70.1 76.45,69.47 76.45,65.79 76.83,65.41 97.03,65.41 99.69,68.07 99.69,79.76 99.06,80.39 96.9,80.39 96.14,81.15 96.14,81.79 95.88,82.04 95.76,82.04 95,82.8 94.11,82.8 93.47,82.17
VDD_DSP_AVS on LY5_PWR: 87.95,81.24 88.71,81.86 91.38,81.87 91.82,82.3 99.82,82.3 100.64,81.48 100.64,80.9 100.71,80.83 100.71,79.5 102.93,77.28 103.51,76.7 103.51,75.06 103.25,74.8 103.25,73.92 103.51,73.66 103.51,73.02 102.48,71.98 102.48,68.97 101.83,68.33 94.49,68.33 93.98,67.82 83.95,67.82 83.57,67.44 76.83,67.44 76.76,67.51 76.76,73.41 77.52,74.17 80.88,74.17
VDD_DSP_SW on TOP: 82.8,60.58 82.8,60.71 81.15,62.36 81.15,64.77 83.44,64.77 83.44,61.21 83.06,60.83 83.06,60.58
VDDS_1V8 on TOP: 74.26,61.21 74.26,54.45 74.18,54.38 71.39,54.38 71.06,54.71 71.06,60.85 71.41,61.21
VDDS_1V8 on BOTTOM: 104.27,75.06 102.74,76.58 102.74,77.34 102.62,77.47 98.42,77.47 96.65,79.25 95,79.25 94.36,79.88 94.36,80.64 94.61,80.9 95.5,80.9 95.63,80.77 96.77,80.77 97.03,81.03 103.89,81.03 107.19,77.72 126.75,77.72 130.81,73.66 130.81,57.66 130.56,57.4 119.13,57.4 116.84,59.69 116.84,65.66 114.81,67.69 111.76,67.69 111.12,68.33 111.12,69.21 106.93,73.41 106.93,74.04 105.92,75.06
VDDS_1V8 on BOTTOM: 88.27,81.66 88.01,81.41 85.6,81.41 84.84,80.64 84.58,80.64 84.33,80.9 84.33,81.66 82.55,81.66 82.17,81.28 82.17,77.34 79.25,77.34 79.25,81.03 80.9,82.68 80.9,84.45 81.66,85.22 83.06,85.22 83.95,86.11 88.01,86.11 88.27,85.85
VDDS_1V8 on BOTTOM: 75.44,61.72 75.44,48.01 97.79,48.01 97.79,40.39 95.25,37.85 89.53,37.85 89.15,37.46 62.86,37.46 62.67,37.66 62.67,38.54 69.34,45.21 69.34,59.56 71.5,61.72
VDDS_1V8 on LY3: 134.37,66.8 141.86,66.8 145.03,69.98 149.61,69.98 152.02,72.39 156.46,72.39 156.84,72.77 156.84,73.91 156.08,74.68 141.48,74.68 138.81,72.01 122.81,72.01 120.65,69.85 120.65,67.18 121.16,66.67 122.43,66.67 123.95,65.15 132.72,65.15
VDDS_1V8 on LY4: 88.01,86.49 87.63,86.11 87.25,86.11 87,85.85 87,85.09 87.5,84.58 89.28,84.58 89.41,84.71 89.79,84.71 90.3,84.2 90.3,80.64 90.68,80.26 91.95,80.26 92.58,80.9 92.2,81.28 92.2,82.3 93.34,82.3 94.11,83.06 95.25,83.06 95.25,84.96 95.88,85.6 96.65,85.6 96.77,85.72 96.77,88.27 96.52,88.52 95.38,88.52 94.87,88.01 91.19,88.01 90.04,89.15 90.04,90.55 88.77,90.55 88.01,89.79
VDDS_1V8 on LY4: 95,51.18 97.16,53.34 115.95,53.34 117.09,54.48 121.67,54.48 122.68,55.5 122.68,58.04 119.25,61.47 119.25,67.18 120.02,67.94 127.63,67.94 128.52,67.06 128.52,55.5 125.6,52.58 125.67,52.51 115.95,42.8 96.77,42.8 95,44.58
VDDS_1V8 on LY5_PWR: 77.22,77.09 82.55,82.42 87.32,82.42 87.35,82.39 88.17,82.39 88.39,82.17 88.39,81.91 87.63,81.15 85.72,81.15 85.47,80.9 85.47,79.55 80.85,74.93 79.38,74.93 79.12,74.68 77.22,74.68 76.2,73.66 76.2,55.12 75.06,53.97 69.34,53.97 66.93,56.39 66.93,74.93 69.09,77.09
VDDS_1V8 on LY5_PWR: 159.64,43.43 160.27,44.07 160.27,112.78 131.32,112.78 130.81,112.27 130.81,107.44 134.11,104.14 143.76,104.14 148.08,99.82 148.08,85.98 148.97,85.09 150.88,85.09 152.15,86.36 156.34,86.36 157.35,85.34 157.35,81.03 154.43,78.1 154.43,55.5 149.35,55.5 147.95,56.9 146.69,56.9 146.18,56.39 146.18,53.85 147.95,52.07 154.43,52.07 154.43,43.81 154.81,43.43
COUT1M on TOP: 2.54,91.82 8.51,91.82 9.65,92.96 10.54,92.96 10.92,92.58 14.73,92.58 14.73,95.5 14.48,95.76 3.94,95.76 2.03,93.85 2.03,92.33
COUT1P on TOP: 14.61,87.38 3.43,87.38 2.03,88.77 2.03,91.06 2.54,91.57 8.38,91.57 9.14,90.8 10.03,90.8 10.67,90.17 14.73,90.17 14.73,87.5
COUT2M on BOTTOM: 2.29,86.74 8.51,86.74 9.27,87.5 10.29,87.5 10.54,87.76 14.73,87.76 14.73,90.68 14.35,91.06 3.81,91.06 1.91,89.15 1.91,87.12
COUT2P on BOTTOM: 14.73,82.55 3.43,82.55 1.91,84.07 1.91,86.11 2.29,86.49 8.25,86.49 9.65,85.09 12.32,85.09 12.83,85.6 14.48,85.6 14.73,85.34
COUT3M on TOP: 2.41,81.66 8.25,81.66 9.65,83.06 11.94,83.06 12.7,82.3 14.48,82.3 14.73,82.55 14.73,85.6 14.48,85.85 3.81,85.85 2.03,84.07 2.03,82.04
COUT3P on TOP: 14.73,77.47 3.56,77.47 2.03,78.99 2.03,81.03 2.41,81.41 8.51,81.41 9.27,80.64 10.03,80.64 10.41,80.26 14.73,80.26
COUT4M on BOTTOM: 2.29,76.58 8.51,76.58 9.27,77.34 10.16,77.34 10.54,77.72 14.73,77.72 14.73,80.64 14.48,80.9 3.81,80.9 1.91,78.99 1.91,76.96
COUT4P on BOTTOM: 2.79,72.77 14.73,72.77 14.73,75.56 12.95,75.56 12.32,74.93 9.65,74.93 8.25,76.33 2.29,76.33 1.91,75.95 1.91,73.66
CS_P on TOP: 50.8,134.49 50.8,130.81 56.26,130.81 56.26,131.7 57.4,131.7 57.4,134.49
HDRV1_N on TOP: 47.5,135.76 47.5,148.08 47.75,148.34 54.48,148.34 54.48,134.75 50.8,134.75 50.8,135.76
HDRV2_N on TOP: 54.74,134.75 54.74,148.34 63.37,148.34 63.37,136.65 63.25,136.65 63.25,135.76 58.93,135.76 58.93,134.75
OUT1M on TOP: 16,91.31 16.13,91.19 20.07,91.19 20.07,91.57 19.81,91.82 19.81,95.12 19.18,95.76 16.38,95.76 16,95.38
OUT1P on TOP: 16.13,86.87 18.54,86.87 19.81,88.14 19.81,90.3 16.13,90.3 16,90.17 16,86.99
OUT2M on BOTTOM: 22.1,87.12 16.64,87.12 16.13,87.63 16.13,90.3 16.38,90.55 20.32,90.55 20.7,90.17 20.7,88.77 21.46,88.01 22.1,88.01 22.35,87.76 22.35,87.38
OUT2P on BOTTOM: 20.45,82.8 20.57,82.93 20.57,84.96 21.34,85.72 22.23,85.72 22.61,86.11 22.61,86.49 22.23,86.87 17.27,86.87 16,85.6 16,82.8
OUT3M on TOP: 20.07,82.8 20.07,83.31 19.81,83.57 19.81,85.34 19.3,85.85 16.38,85.85 16,85.47 16,82.8
OUT3P on TOP: 16,77.47 18.03,77.47 19.56,78.99 19.56,79.76 20.07,80.26 20.07,81.91 19.94,82.04 17.27,82.04 16,80.77
OUT4M on BOTTOM: 22.23,78.74 19.18,78.74 18.16,77.72 16.38,77.72 16,78.1 16,80.52 17.65,82.17 20.19,82.17 20.45,81.91 20.45,80.52 21.21,79.76 22.23,79.76
OUT4P on BOTTOM: 16.26,72.77 19.05,72.77 20.57,74.3 20.57,76.45 22.1,77.98 22.1,78.23 21.84,78.49 19.3,78.49 16.26,75.44 16.13,75.44 16.13,72.9
VAUDIO_9V0 on TOP: 150.11,39.12 150.11,39.88 150.62,40.39 153.54,40.39 153.8,40.13 153.8,38.61 153.67,38.48 150.75,38.48
VAUDIO_9V0 on LY4: 153.16,40.39 155.45,40.39 156.97,38.86 160.15,38.86 162.81,36.19 162.81,24.13 149.48,10.79 0.76,10.79 0.76,61.72 2.41,63.37 11.43,63.37 13.21,61.59 13.21,15.11 145.41,15.11 156.46,26.16 156.46,35.69 155.45,36.7 153.67,36.7 152.65,37.72 152.65,39.88
VCAM_9V0 on TOP: 166.37,27.43 166.12,27.18 166.12,24.76 166.62,24.26 168.27,24.26 168.78,24.76 168.78,27.3 168.66,27.43
VCAM_9V0 on TOP: 154.43,38.61 154.43,40 153.54,40.89 153.54,42.04 153.92,42.42 155.45,42.42 155.83,42.04 155.83,41.66 156.21,41.27 156.21,39.37 155.83,39.37 155.07,38.61
VCAM_9V0 on BOTTOM: 154.69,38.48 159.77,38.48 163.07,35.18 163.07,27.3 164.85,25.53 168.15,25.53 168.53,25.91 168.53,34.16 162.18,40.51 154.94,40.51 154.43,40 154.43,38.73
VDA_PCIE_FIL1V8 on LY4: 91.31,89.28 91.31,88.52 91.57,88.27 94.36,88.27 94.49,88.39 94.49,89.53 93.98,90.04 92.08,90.04
VDA_PHY_1V8 on LY3: 95.44,88.71 95.64,88.52 96.65,88.52 97.16,89.03 97.16,92.84 96.58,93.41 96.59,93.42 94.67,93.42 94.67,93.4 94.65,93.38 94.65,88.99 94.93,88.71
VDISP_16V0 on TOP: 164.08,57.66 164.08,55.75 164.85,54.99 167.13,54.99 167.64,55.5 167.64,57.02 166.75,57.91 164.34,57.91
VDISP_16V0 on TOP: 144.53,36.45 144.53,39.37 144.02,39.88 142.24,39.88 141.73,39.37 141.73,37.08 142.37,36.45
VDISP_16V0 on LY4: 168.78,58.42 168.66,58.55 165.99,58.55 164.08,56.64 164.08,50.8 158.75,45.47 149.1,45.47 147.32,43.69 145.67,43.69 143.76,41.78 143.76,39.88 142.37,39.88 141.6,39.12 141.6,36.32 142.37,35.56 150.62,35.56 152.15,37.08 152.15,40.13 152.78,40.77 155.7,40.77 157.1,39.37 165.74,39.37 168.78,42.42
VIO_3V3 on TOP: 77.34,37.59 75.56,37.59 74.42,36.45 74.42,35.05 75.95,35.05 76.2,35.31 77.47,35.31 77.85,35.69 77.85,37.08
VIO_3V3 on TOP: 104.01,117.09 104.01,119.38 103.76,119.63 103.76,120.78 103.89,120.9 106.17,120.9 106.3,120.78 106.3,117.98 105.41,117.09
VIO_3V3 on BOTTOM: 111.63,158.88 117.6,158.88 120.14,156.34 120.14,150.37 117.6,150.37 116.97,149.73 114.3,149.86 109.98,154.18 109.98,157.23
VIO_3V3 on BOTTOM: 89.66,82.68 89.66,82.17 90.3,81.53 90.3,80.77 89.03,80.77 88.27,80.01 88.27,78.61 87.88,78.23 85.34,78.23 85.22,78.36 85.22,80.9 85.47,81.15 88.01,81.15 88.52,81.66 88.52,83.44 88.9,83.44
VIO_3V3 on LY3: 89.15,91.19 89.15,91.69 89.53,92.07 90.3,92.07 91,92.77 91,94.11 91.03,94.14 91.03,94.84 91.31,95.12 94.11,95.12 94.3,94.93 94.3,89.22 93.73,88.65 91.19,88.65 90.68,88.14 89.92,88.14 89.53,87.76 89.53,85.6 89.15,85.22 89.15,84.96 89.53,84.58 89.53,83.82 89.03,83.31 89.03,81.66 89.28,81.41 90.3,81.41 90.93,80.77 91.44,80.77 92.08,81.41 95,81.41 95.76,80.64 96.52,80.64 96.9,81.03 96.9,81.41 96.77,81.53 96.52,81.53 95.76,82.3 95.76,82.55 96.39,83.19 96.39,84.58 96.65,84.84 97.41,84.84 97.66,84.58 97.66,79.63 97.28,79.25 95.25,79.25 94.61,79.88 89.15,79.88 87.88,81.15 87.88,81.91 87.38,82.42 85.72,82.42 83.19,79.88 77.47,79.88 76.45,80.9 76.45,82.68 77.34,83.57 87.76,83.57 87.76,84.84 88.39,85.47 88.39,90.42
VIO_3V3 on LY4: 77.85,37.21 77.85,33.02 72.39,27.56 34.16,27.56 26.29,35.43 26.29,57.28 29.08,60.07 51.43,60.07 51.43,59.69 53.85,57.28 55.37,57.28 60.07,52.58 63.88,52.58 65.66,50.8 65.66,38.73 66.55,37.85 77.22,37.85
VIO_3V3 on LY4: 95.5,82.55 95.76,82.3 96.01,82.3 96.27,82.04 96.27,81.28 96.77,80.77 98.04,80.77 98.42,80.39 99.95,80.39 99.96,73.15 101.35,71.76 101.35,71.75 115.06,71.75 115.44,72.14 115.44,75.95 110.24,81.15 101.73,81.15 100.84,82.04 99.06,82.04 98.42,82.68 98.42,84.71 98.81,85.09 111,85.09 113.54,87.63 113.54,99.19 112.27,100.46 104.9,100.46 97.66,93.22 97.66,91.19 97.03,90.55 97.03,85.6 96.77,85.34 96.01,85.34 95.5,84.84
VIO_3V3 on LY5_PWR: 98.55,123.82 98.55,143.89 107.44,152.78 148.46,152.78 160.53,140.72 160.53,132.08 161.42,131.19 161.42,130.05 160.15,128.78 160.15,113.16 130.94,113.16 130.18,112.39 130.18,107.06 133.6,103.63 143.51,103.63 147.7,99.44 147.7,85.6 148.72,84.58 151.13,84.58 152.53,85.98 155.96,85.98 156.97,84.96 156.97,81.41 153.86,78.3 153.86,60.39 153.8,60.32 153.92,60.2 153.92,55.88 149.61,55.88 148.21,57.28 146.3,57.28 145.41,56.39 145.41,53.72 147.45,51.69 153.92,51.69 153.92,32.38 140.59,32.38 140.59,10.79 78.49,10.79 78.49,33.4 70.23,33.4 70.23,42.16 112.9,42.16 112.9,93.34 111.63,94.61 101.35,94.61 100.08,93.34 93.22,93.34 93.22,105.79 97.79,105.79 103.12,111.12 103.12,119.25
VIO_3V3 on LY5_PWR: 42.04,56.52 29.08,56.52 28.07,57.53 28.07,96.52 16.38,96.52 13.08,99.82 13.08,100.97 17.78,105.66 43.31,105.66 43.31,103.38 42.04,102.11
VIO_3V3_SD on LY3: 148.08,133.73 148.08,127.51 148.97,126.62 154.69,126.62 156.34,128.27 156.34,132.72 155.07,133.99 148.34,133.99
VMEDIA_16V0 on TOP: 143,14.6 143,11.94 143.13,11.81 146.43,11.81 146.94,12.32 146.94,13.21 145.54,14.6
VMEDIA_16V0 on BOTTOM: 121.67,22.48 121.67,13.84 123.89,11.62 147.19,11.62 147.19,16 145.29,17.91 127.63,17.91 125.98,19.56 125.98,22.61 125.35,23.24 122.43,23.24
VPOC_DISPLAY on TOP: 165.23,58.17 162.69,58.17 161.67,59.18 161.67,60.83 162.05,61.21 164.21,61.21 165.48,59.94 165.48,58.42
VPOC_DISPLAY on LY4: 166.12,59.31 166.88,60.07 166.88,70.23 165.48,71.63 160.15,71.63 160.08,71.56 155,71.56 153.92,70.48 153.92,62.61 157.23,59.31
VSW_3V3 on TOP: 68.83,42.67 66.8,42.67 66.55,42.93 62.61,42.93 61.47,44.07 61.47,45.21 61.98,45.72 64.01,45.72 64.13,45.85 64.13,47.24 63.63,47.75 63.63,48.64 67.69,48.64 68.58,47.75 68.58,43.94 68.83,43.69
VSW_5V0 on TOP: 77.34,30.1 75.56,30.1 74.42,28.96 74.42,27.56 75.95,27.56 76.2,27.81 77.47,27.81 77.85,28.19 77.85,29.59
VSW_5V0 on TOP: 92.71,26.92 94.74,26.92 95.25,26.42 95.25,24.13 94.74,23.62 93.34,23.62 92.71,24.26
VSW_5V0 on LY4: 74.93,29.34 74.93,26.8 75.56,26.16 88.39,26.16 90.68,23.88 94.74,23.88 95.5,24.64 95.5,26.54 94.61,27.43 90.8,27.43 88.77,29.46 84.84,29.46 83.57,30.73 76.33,30.73
VSW_5V0 on LY5_PWR: 78.11,33.02 78.11,10.79 63.12,10.79 63.12,24 63.63,24.51 70.1,24.51 70.23,24.64 70.23,33.02
VSYS_3V3 on TOP: 87,115.82 93.6,115.82 94.61,114.81 95.63,114.81 96.65,115.82 96.65,122.43 97.22,123 102.81,123 103.5,122.3 103.5,120.14 102.62,119.25 102.62,116.84 100.08,116.84 99.44,116.2 99.44,112.9 98.55,112.01 87,112.01
VSYS_3V3 on TOP: 90.3,35.18 90.3,37.97 90.55,38.23 94.36,38.23 94.74,37.85 94.74,36.32 94.49,36.07 91.57,36.07 91.19,35.69 91.19,35.18
VSYS_3V3 on TOP: 68.83,41.27 68.83,38.99 68.33,38.48 67.06,38.48 66.67,38.86 66.67,41.02 66.93,41.27
VSYS_3V3 on BOTTOM: 96.01,119.89 101.35,119.89 101.73,119.51 101.73,118.36 99.95,116.59 96.65,116.59 95.76,117.47 95.76,119.63
VSYS_3V3 on LY4: 135.51,53.72 139.95,53.72 141.22,52.45 141.22,50.93 139.7,49.4 139.7,48.39 143.26,44.83 143.26,40.39 142.11,40.39 139.7,37.97 125.86,37.97 120.65,32.77 111.76,32.77 110.87,33.65 89.92,33.65 89.28,33.02 88.01,33.02 87.38,33.65 82.55,33.65 77.85,38.35 66.93,38.35 66.17,39.12 66.17,50.16 68.96,52.96 78.74,52.96 80.01,54.23 80.01,58.42 82.93,61.34 89.53,61.34 94.23,56.64 94.23,43.18 97.66,39.75 104.39,39.75 104.9,40.26 106.68,40.26 107.95,38.99 112.9,38.99 113.28,38.61 117.73,38.61 122.05,42.93 124.08,42.93 128.4,47.24 132.21,47.24 133.35,48.39 133.35,51.56
VSYS_3V3 on LY5_PWR: 90.8,52.32 92.08,53.59 92.08,66.8 91.95,66.93 76.96,66.93 76.96,53.97 78.61,53.97 80.26,52.32
VSYS_3V3 on LY5_PWR: 69.72,42.04 43.31,42.04 41.91,43.43 41.91,55.75 29.21,55.75 27.69,57.28 27.69,96.14 16.13,96.14 12.7,99.57 12.7,101.09 17.78,106.17 97.41,106.17 102.62,111.38 102.62,118.75 98.04,123.32 98.04,130.05 30.86,130.05 30.86,168.66 0.76,168.66 0.76,10.79 62.61,10.79 62.61,24.26 63.37,25.02 63.5,24.89 69.72,24.89
VSYS_5V0 on TOP: 89.03,34.92 83.82,34.92 83.19,35.56 83.19,40.13 81.91,41.4 69.6,41.4 69.6,40.64 70.99,39.24 80.14,39.24 80.9,38.48 80.9,33.53 83.82,30.61 85.6,30.61 85.98,30.99 85.98,32.89 86.23,33.15 87.63,33.15 87.63,34.16 88.01,34.54 89.03,34.54
VSYS_5V0 on TOP: 92.71,28.32 92.71,30.61 93.22,31.11 94.49,31.11 94.87,30.73 94.87,28.57 94.61,28.32
VSYS_5V0 on LY4: 134.62,37.34 134.62,23.75 131.95,21.08 114.68,21.08 111.38,24.38 101.85,24.38 98.42,27.81 90.93,27.81 88.9,29.84 85.09,29.84 83.57,31.37 83.57,32.64 84.2,33.27 87.5,33.27 88.14,32.64 89.41,32.64 90.04,33.27 110.49,33.27 111.38,32.38 120.78,32.38 125.86,37.46 131.44,37.46 131.57,37.59 134.37,37.59
VSYS_10V5 on TOP: 161.8,24.38 162.31,24.89 162.31,26.03 161.67,26.67 154.56,26.67 154.05,27.18 154.05,29.72 154.81,30.48 154.81,32.38 151.26,32.38 150.24,31.37 150.24,25.78 151.64,24.38
VSYS_10V5 on LY4: 155.96,26.42 145.03,15.49 13.59,15.49 13.59,108.33 28.45,123.19 50.93,123.19 52.32,121.79 52.32,119.89 49.4,116.97 31.11,116.97 18.8,104.65 18.8,30.1 28.32,20.57 143,20.57 151.38,28.96 155.19,28.96 155.96,28.19
VSYS_16V0 on TOP: 142.88,18.67 142.88,25.02 145.8,25.02 145.8,19.3 145.16,18.67
VSYS_16V0 on TOP: 92.33,144.14 92.33,146.81 92.58,147.07 94.23,147.07 94.93,147.76 94.93,151.96 93.73,153.16 91.57,153.16 91.31,152.91 91.31,146.94 91.06,146.69 91.06,144.14
VSYS_16V0 on TOP: 144.65,32.38 144.65,26.03 141.73,26.03 141.73,31.75 142.37,32.38
VSYS_16V0 on TOP: 59.18,129.16 59.18,135.51 69.85,135.51 70.74,134.62 70.74,129.16
VSYS_16V0 on TOP: 159.13,17.27 165.1,17.27 165.74,17.91 165.74,20.57 165.61,20.7 162.18,20.7 161.67,20.19 161.67,18.92 161.42,18.67 159.13,18.67
VSYS_16V0 on BOTTOM: 63.5,129.54 63.5,132.72 63.75,132.97 70.61,132.97 70.87,132.72 70.87,129.54
VSYS_16V0 on LY5_PWR: 140.97,32 140.97,10.79 169.42,10.79 169.42,168.66 31.5,168.66 31.5,130.56 98.04,130.56 98.04,144.02 107.31,153.29 148.72,153.29 161.04,140.97 161.04,132.21 161.8,131.44 161.8,129.67 160.66,128.52 160.66,42.93 154.43,42.93 154.43,32
VTT_DDR on TOP: 62.48,53.09 62.99,52.58 62.99,50.8 62.74,50.8 62.74,51.56 62.61,51.69 58.93,51.69 58.67,51.94 58.67,52.58 59.56,53.47 60.07,53.47 60.2,53.59 60.2,59.44 58.67,60.96 58.67,65.15 58.17,65.66 47.88,65.66 47.62,65.91 47.62,70.74 47.88,70.99 64.52,70.99 66.17,69.34 66.17,66.04 62.48,62.36
VTT_DDR on BOTTOM: 47.12,69.09 47.12,70.23 47.88,70.99 64.39,70.99 64.9,70.48 64.9,69.09 64.52,68.71 47.5,68.71
VTUN_1V8 on TOP: 62.23,34.42 62.23,32 62.99,31.24 64.9,31.24 66.04,32.38 66.04,34.04 65.53,34.54 62.36,34.54
VTUN_1V8 on LY3: 64.9,30.73 61.21,30.73 54.23,37.72 54.23,46.35 53.59,46.99 40.64,46.99 33.66,53.97 33.66,57.66 34.29,58.29 42.29,58.29 45.21,55.37 50.93,55.37 52.2,56.64 59.94,56.64 65.15,51.43 65.15,30.99
VTUN_1V8_OUT on TOP: 72.39,35.05 66.29,35.05 66.04,35.31 66.04,36.96 65.66,37.34 65.66,38.23 71.63,38.23 72.39,37.46
VTUN_3V3 on TOP: 62.23,26.92 62.23,24.51 63.12,23.62 64.77,23.62 66.04,24.89 66.04,26.54 65.53,27.05 62.36,27.05
VTUN_3V3 on LY3: 23.11,22.86 19.3,26.67 19.3,36.83 24.77,42.29 33.27,42.29 37.72,46.74 53.09,46.74 53.85,45.97 53.85,37.59 61.21,30.23 65.79,30.23 67.06,28.96 67.06,25.02 64.9,22.86
VTUN_3V3_OUT on TOP: 72.39,27.56 66.29,27.56 66.04,27.81 66.04,29.46 65.66,29.84 65.66,30.73 71.63,30.73 72.39,29.97
VUSB_5V0 on TOP: 124.97,147.7 124.08,147.7 124.08,146.43 123.19,145.54 123.19,144.14 122.94,143.89 122.94,139.57 123.32,139.19 124.46,139.19 124.97,139.7
VUSB_5V0 on TOP: 88.01,142.75 81.79,142.75 81.79,150.75 84.58,150.75 84.58,145.16 84.96,144.78 88.01,144.78
VUSB_5V0 on LY3: 160.78,149.48 158.12,152.15 147.47,152.15 141.68,146.35 112.6,146.35 112.59,146.37 106.24,146.37 104.2,148.4 98.49,148.4 95.12,151.76 84.2,151.76 82.3,149.86 82.3,143.89 85.47,140.72 98.42,140.72 102.36,136.78 155.47,136.78 160.78,142.09
N29751238 on TOP: 13.33,104.14 14.35,104.14 14.99,103.5 16.51,103.5 16.51,104.78 18.16,106.43 18.16,107.31 17.91,107.57 15.88,107.57 15.62,107.31 15.62,106.3 15.37,106.04 14.86,106.04 14.61,106.3 13.59,106.3 13.08,105.79 13.08,104.39
N29751250 on TOP: 6.6,105.28 6.6,106.55 9.91,106.55 9.91,107.44 12.19,107.44 12.32,107.31 12.32,104.39 12.06,104.14 11.05,104.14 9.91,105.28
N29756671 on TOP: 110.24,19.68 110.24,22.73 111.12,22.73 111.12,25.27 111.38,25.53 113.28,25.53 113.28,19.68
N29776322 on TOP: 166.88,27.94 162.31,27.94 160.91,29.34 160.91,33.02 168.27,33.02 168.27,29.34
N29776336 on TOP: 160.91,34.8 160.91,37.97 163.07,40.13 167.39,40.13 168.27,39.24 168.27,34.8
N29776342 on TOP: 163.07,40.39 167.89,40.39 167.89,42.16 163.58,42.16 162.94,41.53 162.94,40.51
N29842389 on LY4: 152.91,57.66 152.91,47.62 152.4,47.12 149.48,47.12 148.84,47.75 148.84,56.64 150.37,58.17 152.4,58.17
N30808408 on TOP: 90.3,34.67 91.44,34.67 92.2,33.91 94.61,33.91 94.61,35.43 91.82,35.43 91.44,35.05 90.3,35.05
N30812993 on TOP: 153.92,18.92 155.57,18.92 155.83,19.18 155.83,21.97 156.34,21.97 156.34,23.11 152.53,23.11 152.53,21.97 153.8,21.97 153.8,19.05
